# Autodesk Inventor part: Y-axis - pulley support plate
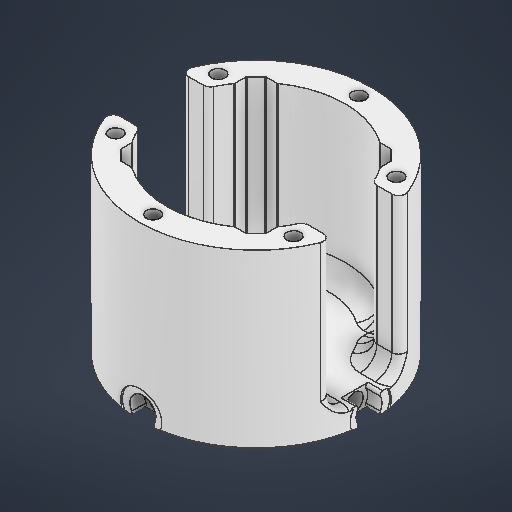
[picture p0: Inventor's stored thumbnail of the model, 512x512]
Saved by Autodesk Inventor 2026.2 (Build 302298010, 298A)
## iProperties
Created: 2026-04
Part Number: Y-axis - pulley support plate
Material: PBT 플라스틱
Document SubType Name: Modeling
Designer: work
Density: 1.31 g/cm^3
Appearance: 매끄러움 - 흰색
Author: work
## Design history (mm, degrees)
sketch "스케치1"
  geometry: L1 (-22, 22)-(22, 22); L2 (22, 22)-(22, -22); L3 (22, -22)-(-22, -22); L4 (-22, -22)-(-22, 22); L5 (-22, 22)-(22, -22); L6 (22, 22)-(-22, -22); L7 (0, 0)-(0, -30); L8 (0, 0)-(25.981, -15); L9 (0, 0)-(25.981, 15); L10 (0, 0)-(0, 30); L11 (0, 0)-(-25.981, 15); L12 (0, 0)-(-25.981, -15); L13 (-32.496, 10)-(32.496, 10); L14 (32.496, 10)-(32.496, -10); L15 (32.496, -10)-(-32.496, -10); L16 (-32.496, -10)-(-32.496, 10); L17 (0, 0)-(34, 0); C1 r 2 at (0, -30); C2 r 2 at (25.981, -15); C3 r 2 at (25.981, 15); C4 r 2 at (0, 30); C5 r 2 at (-25.981, 15); C6 r 2 at (-25.981, -15); C7 r 26 at (0, 0); A1 r 34 centre (0, 0) between (-32.496, 10) and (32.496, -10); 7 further points
  constraints: 34 end point, 10 coincident, 8 centre point, 4 parallel, 3 horizontal, 3 midpoint, 3 point on circle, 3 point on line, 2 perpendicular, 1 vertical, 32 other
  dimensions: "d0" = 44 distance of L2.end L3.end; "d1" = 44 distance of L1.end L2.end; "d2" = 30 distance of L7.start L7.end; "d3" = 4 diameter of C1; "d6" = 360 deg dimension on L7.start L7.end (derived); "d8" = 8 radial gap between concentric circles of A1 C7; "d9" = 4 dimension on C7; "d10" = 20 distance of L13.end L14.end
extrude "돌출1" new body sketch "스케치1" distance "d11" = 45; taper "d12" = 0 deg
sketch "스케치2"
  geometry: L1 (0, 0)-(34, 0); L2 (0, 0)-(24.042, -24.042); L3 (0, 0)-(24.042, 24.042); C1 r 12.75 at (0, 0); A1 r 34 centre (0, 0) between (-32.496, -10) and (32.496, -10) reference; A2 r 34 centre (0, 0) between (32.496, -10) and (34, 0); 2 further points
  constraints: 6 end point, 4 point on circle, 2 centre point, 2 coincident, 1 horizontal, 1 perpendicular
  dimensions: "d13" = 25.5 diameter of C1; "d14" = 45 deg angle of L2 L1
extrude "돌출2" join sketch "스케치2" distance "d15" = 6; taper "d16" = 0 deg
node "작업 평면1"
sketch "스케치3"
  geometry: L1 (-34, -6)-(34, -6) reference; L2 (0, -6)-(0, -3); C1 r 6 at (0, -3); 1 further point
  constraints: 2 end point, 1 centre point, 1 midpoint, 1 vertical
  dimensions: "d20" = 12 diameter of C1; "d33" = 3 distance of L2.start L2.end
extrude "돌출3" cut sketch "스케치3" distance "d18" = 1; taper "d19" = 0 deg
sketch "스케치6"
  geometry: A1 r 6 centre (0, -3) between (5.196, -6) and (-5.196, -6) reference; 2 further points
  constraints: 1 coincident
hole "구멍2" sketch "스케치6" at (0, -3) diameter "d34" = 5; stored, may be unused: countersink angle "d38" = 90 deg, drill point angle "d40" = 0 deg; dims "d35" = 8, "d36" = 7.6, "d37" = 4.2, "d39" = 8
chamfer "모따기1" distance "d45" = 1; stored, may be unused: second distance "d46" = 2, angle "d47" = 45 deg
sketch "스케치7"
  geometry: L1 (-21.25, -21.25)-(21.25, -21.25); L2 (21.25, -21.25)-(21.25, 21.25); L3 (21.25, 21.25)-(-21.25, 21.25); L4 (-21.25, 21.25)-(-21.25, -21.25); L5 (-21.25, -21.25)-(21.25, 21.25); L6 (21.25, -21.25)-(-21.25, 21.25); L7 (-21.25, 18.348)-(-18.348, 21.25); L8 (18.348, -21.25)-(21.25, -18.348); L9 (-18.348, -21.25)-(-21.25, -18.348); L10 (21.25, -18.348)-(18.348, -21.25); L11 (18.348, 21.25)-(21.25, 18.348); 12 further points
  constraints: 22 end point, 4 midpoint, 2 parallel, 2 point on line, 2 symmetric about line, 1 horizontal, 1 perpendicular, 17 other
  dimensions: "d48" = 42.5 distance of L3.end L2.end; "d49" = 42.5 distance of L2.end L1.end; "d50" = 45 deg angle of L3 L7; "d51" = 56 distance of point (19.799, -19.799) point (-19.799, 19.799); "d54" = 360 deg dimension on point (0, 0) L7.start (derived)
extrude "돌출5" cut sketch "스케치7" stored distance "d56" = 10; taper "d57" = 0 deg
node "작업 평면2"
sketch "스케치8"
  geometry: L1 (14.981, -21.25)-(18.348, -21.25) reference; L2 (18.348, -21.25)-(21.25, -18.348) reference; L3 (21.25, -18.348)-(21.25, -14.981) reference; L4 (-32.496, -10)-(-24, -10) reference; L5 (24, -10)-(32.496, -10) reference; L6 (-21.25, -14.981)-(-21.25, -18.348) reference; L7 (-21.25, -18.348)-(-18.348, -21.25) reference; L8 (-18.348, -21.25)-(-14.981, -21.25) reference; L9 (21.25, 14.981)-(21.25, 18.348) reference; L10 (21.25, 18.348)-(18.348, 21.25) reference; L11 (18.348, 21.25)-(14.981, 21.25) reference; L12 (-14.981, 21.25)-(-18.348, 21.25) reference; L13 (-18.348, 21.25)-(-21.25, 18.348) reference; L14 (-21.25, 18.348)-(-21.25, 14.981) reference; L15 (32.496, 10)-(24, 10) reference; L16 (-24, 10)-(-32.496, 10) reference; L17 (14.981, -21.25)-(18.348, -21.25) reference; L18 (18.348, -21.25)-(21.25, -18.348) reference; L19 (21.25, -18.348)-(21.25, -14.981) reference; L20 (24, -10)-(32.496, -10) reference; L21 (-32.496, -10)-(-24, -10) reference; L22 (-21.25, -14.981)-(-21.25, -18.348) reference; L23 (-21.25, -18.348)-(-18.348, -21.25) reference; L24 (-18.348, -21.25)-(-14.981, -21.25) reference; L25 (-21.25, 18.348)-(-21.25, 14.981) reference; L26 (-24, 10)-(-32.496, 10) reference; L27 (32.496, 10)-(24, 10) reference; L28 (21.25, 14.981)-(21.25, 18.348) reference; L29 (21.25, 18.348)-(18.348, 21.25) reference; L30 (18.348, 21.25)-(14.981, 21.25) reference; L31 (-14.981, 21.25)-(-18.348, 21.25) reference; L32 (-18.348, 21.25)-(-21.25, 18.348) reference; C1 r 2 at (25.981, -15) reference; C2 r 2 at (-25.981, -15) reference; C3 r 2 at (0, -30) reference; C4 r 2 at (25.981, 15) reference; C5 r 2 at (0, 30) reference; C6 r 2 at (-25.981, 15) reference; A1 r 26 centre (0, 0) between (21.25, -14.981) and (24, -10) reference; A2 r 34 centre (0, 0) between (-32.496, -10) and (32.496, -10) reference; A3 r 26 centre (0, 0) between (-24, -10) and (-21.25, -14.981) reference; A4 r 26 centre (0, 0) between (-14.981, -21.25) and (14.981, -21.25) reference; A5 r 26 centre (0, 0) between (14.981, 21.25) and (-14.981, 21.25) reference; A6 r 26 centre (0, 0) between (-21.25, 14.981) and (-24, 10) reference; A7 r 34 centre (0, 0) between (-32.496, -10) and (32.496, -10) reference; A8 r 26 centre (0, 0) between (24, 10) and (21.25, 14.981) reference; A9 r 34 centre (0, 0) between (32.496, 10) and (-32.496, 10) reference; A10 r 26 centre (0, 0) between (21.25, -14.981) and (24, -10) reference; A11 r 26 centre (0, 0) between (-24, -10) and (-21.25, -14.981) reference; A12 r 26 centre (0, 0) between (-14.981, -21.25) and (14.981, -21.25) reference; A13 r 26 centre (0, 0) between (-21.25, 14.981) and (-24, 10) reference; A14 r 34 centre (0, 0) between (32.496, 10) and (-32.496, 10) reference; A15 r 26 centre (0, 0) between (24, 10) and (21.25, 14.981) reference; A16 r 26 centre (0, 0) between (14.981, 21.25) and (-14.981, 21.25) reference; 2 further points
extrude "돌출6" join sketch "스케치8" stored distance "d59" = 10; taper "d60" = 0 deg
fillet "모깎기2" dims "d61" = 0.75
fillet "모깎기3" dims "d62" = 2
fillet "모깎기4" dims "d63" = 0.5
fillet "모깎기5" dims "d64" = 4.9
feature "͉耀͋耀͍耀͏耀͑耀͓耀͕耀͗耀" dims "d0" = 44, "d1" = 44, "d2" = 30, "d3" = 4, "d4" = 60, "d6" = 360 deg (derived), "d8" = 8, "d9" = 4, "d10" = 20, "d11" = 45, "d12" = 0, "d13" = 25.5, "d14" = 45 deg, "d15" = 6, "d16" = 0, "d18" = 1, "d19" = 0, "d20" = 12, "d33" = 3, "d34" = 5, "d35" = 8, "d36" = 7.6, "d37" = 4.2, "d38" = 90 deg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
node "솔리드1"
pattern_circular "원형 패턴2" dims "d42" = 360 deg
node "스케치 - 원형 패턴1" dims "d6" = 360 deg (derived)
node "스케치 - 원형 패턴2" dims "d54" = 360 deg (derived)
node "투영된 루프1"
node "투영된 루프2"
feature "A9D066F2-1C7D-4E18-AEED-F7BC21143FA4" dims "d34" = 5, "d35" = 8, "d36" = 7.6, "d37" = 4.2, "d38" = 90 deg, "d39" = 8, "d40" = 0
